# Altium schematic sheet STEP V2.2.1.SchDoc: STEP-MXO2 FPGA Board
size A3; Revision: V2.2; SheetNumber: 2; SheetTotal: 2; PageSetup: Record=PageOptions¦CenterHorizontal=True¦CenterVertical=True¦PrintScale=0.69¦XCorrection=1.00¦YCorrection=1.00¦PrintKind=0¦BorderSize=5000000¦LeftOffset=0¦BottomOffset=0¦Orientation=2¦PaperLength=1000¦PaperWidth=1000¦Scale=100¦PaperSource=7¦PrintQuality=-3¦MediaType=1¦DitherType=10¦PrintScaleMode=1¦PaperKind=A4¦PaperIndex=9; Function: FPGA,LEDs,Buttons,Switchs,RGB LEDs,Segments
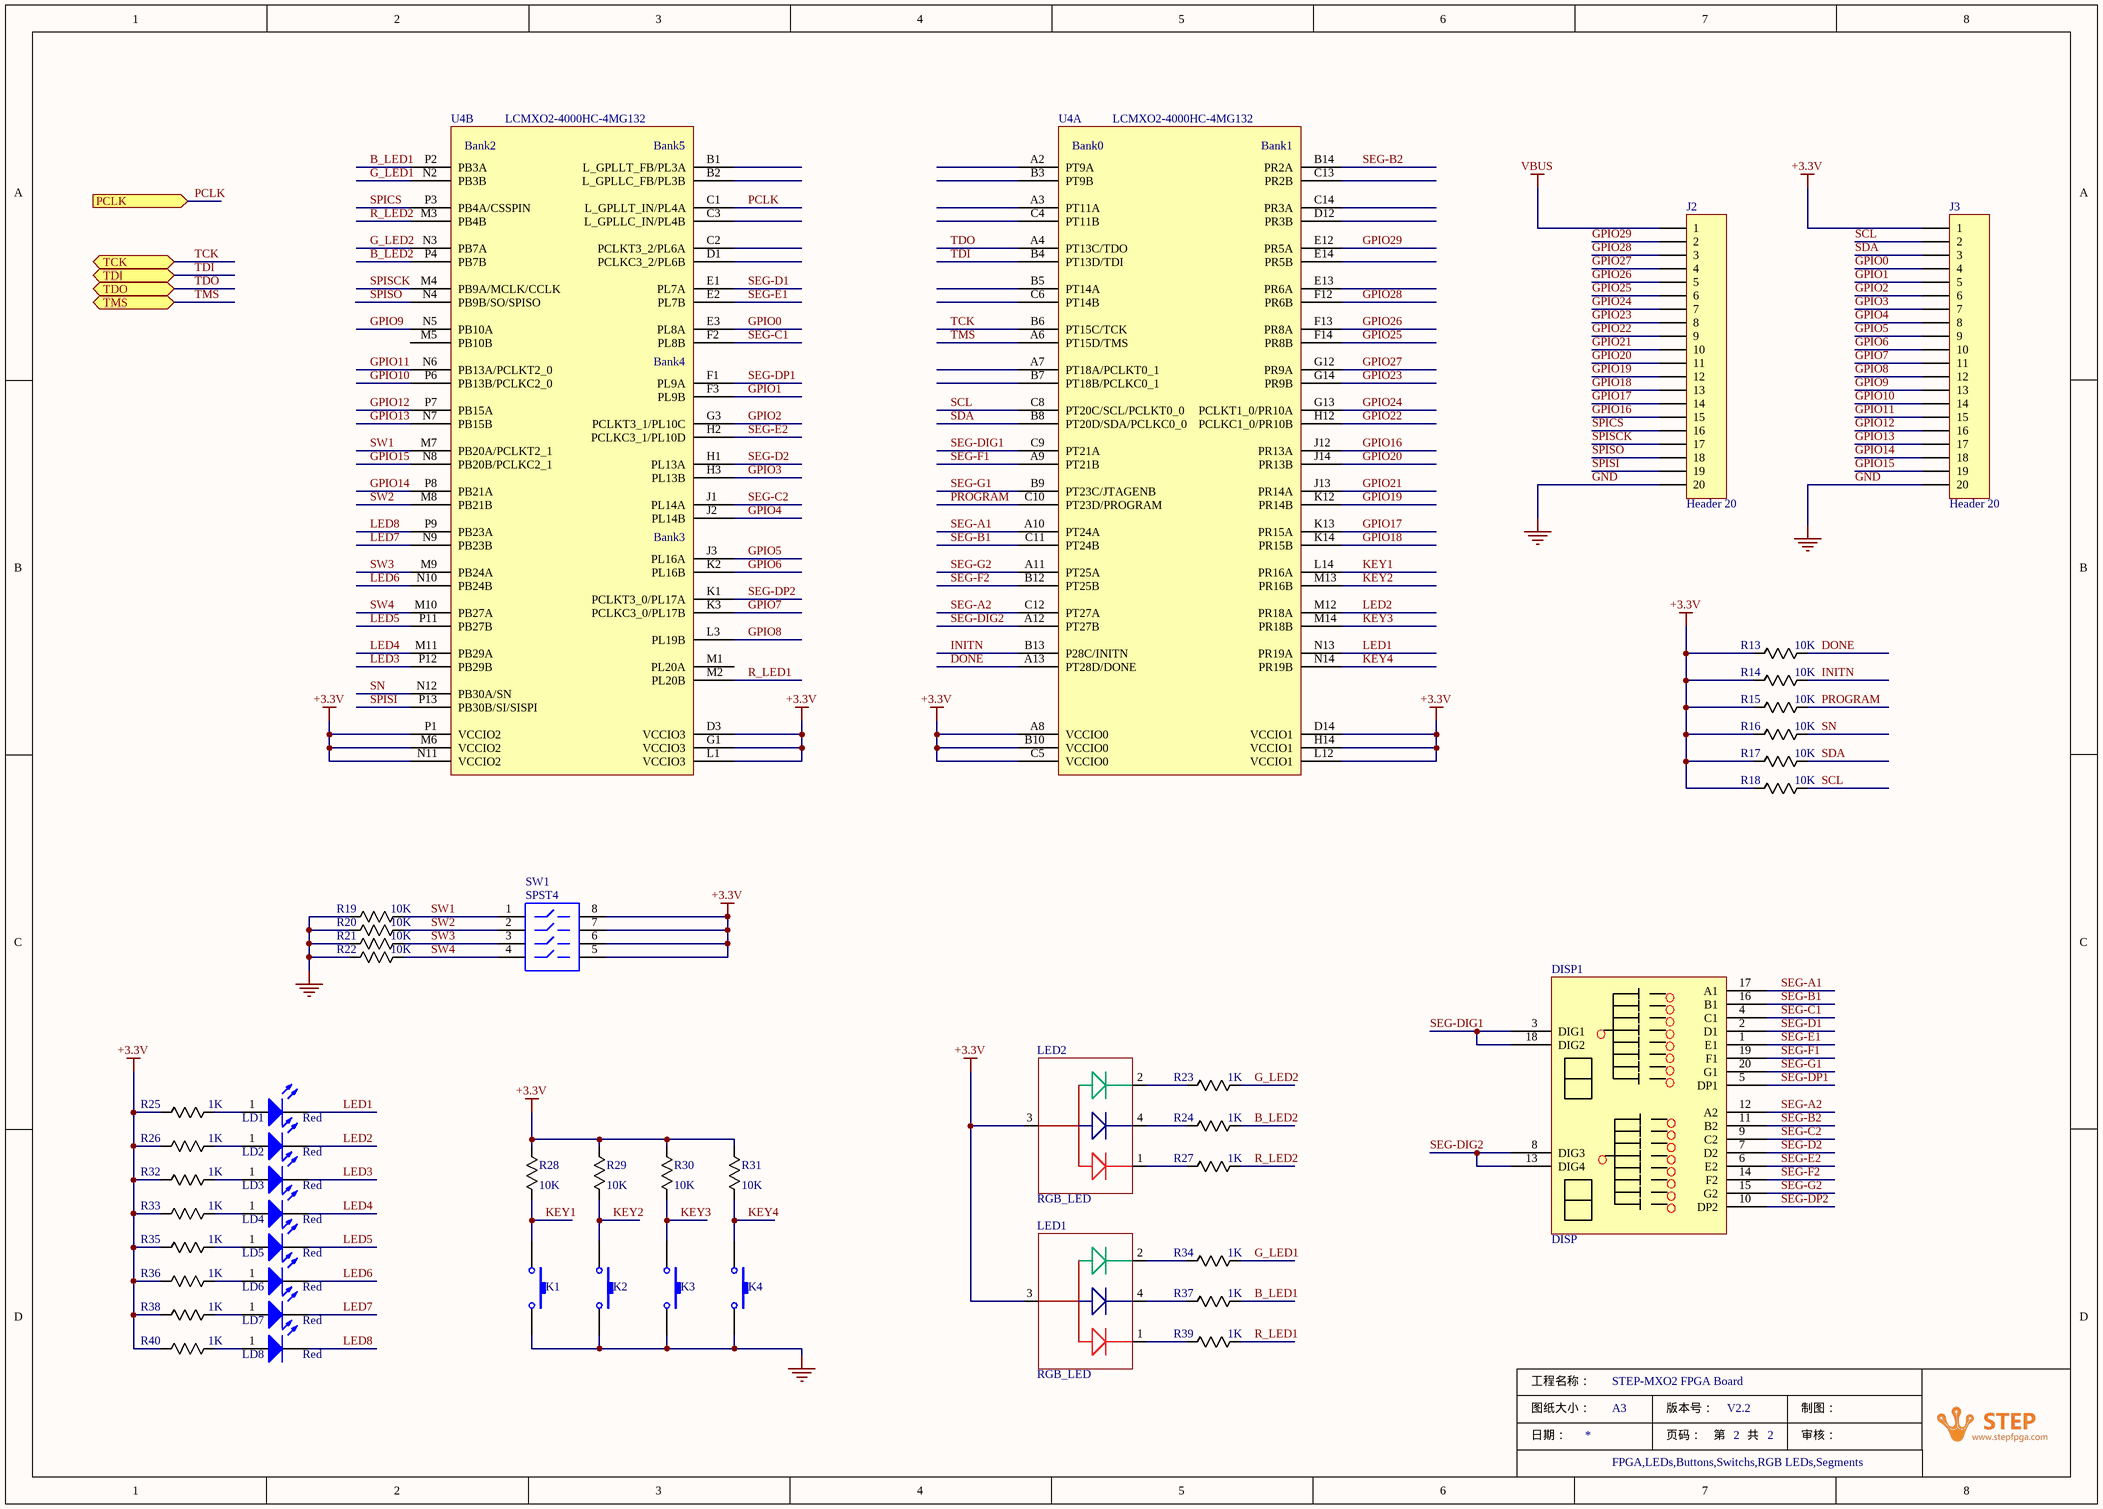
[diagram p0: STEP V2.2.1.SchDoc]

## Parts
DISP1  DISP  [SMD_LED_2*8bit_10*14]
J2  Header 20  [HDR1X20]
J3  Header 20  [HDR1X20]
K1  SW-PB  [SMD_KEY_3x4x2]  (value not drawn)
K2  SW-PB  [SMD_KEY_3x4x2]  (value not drawn)
K3  SW-PB  [SMD_KEY_3x4x2]  (value not drawn)
K4  SW-PB  [SMD_KEY_3x4x2]  (value not drawn)
LD1  Red  [LED0603]
LD2  Red  [LED0603]
LD3  Red  [LED0603]
LD4  Red  [LED0603]
LD5  Red  [LED0603]
LD6  Red  [LED0603]
LD7  Red  [LED0603]
LD8  Red  [LED0603]
LED1  RGB_LED  [SMD_RGB_LED_1.5*1.6]
LED2  RGB_LED  [SMD_RGB_LED_1.5*1.6]
R13  10K  [R0201]
R14  10K  [R0201]
R15  10K  [R0201]
R16  10K  [R0201]
R17  10K  [R0201]
R18  10K  [R0201]
R19  10K  [R0201]
R20  10K  [R0201]
R21  10K  [R0201]
R22  10K  [R0201]
R23  1K  [R0201]
R24  1K  [R0201]
R25  1K  [R0201]
R26  1K  [R0201]
R27  1K  [R0201]
R28  10K  [R0201]
R29  10K  [R0201]
R30  10K  [R0201]
R31  10K  [R0201]
R32  1K  [R0201]
R33  1K  [R0201]
R34  1K  [R0201]
R35  1K  [R0201]
R36  1K  [R0201]
R37  1K  [R0201]
R38  1K  [R0201]
R39  1K  [R0201]
R40  1K  [R0201]
SW1  SPST4  [SMD_KEY_4]
U4  LCMXO2-4000HC-4MG132  [CSBGA132]  (parts A,B of 3)

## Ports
PCLK (in), TCK (bidir), TDI (bidir), TDO (bidir), TMS (bidir)

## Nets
+3.3V: J3.1 LED1.3(COMMON_ANODE) LED2.3(COMMON_ANODE) R13.1 R14.1 R15.1 R16.1 R17.1 R18.1 R25.2 R26.2 R28.2 R29.2 R30.2 R31.2 R32.2 R33.2 R35.2 R36.2 R38.2 R40.2 SW1.5 SW1.6 SW1.7 SW1.8 U4.A8(VCCIO0) U4.B10(VCCIO0) U4.C5(VCCIO0) U4.D3(VCCIO3) U4.D14(VCCIO1) U4.G1(VCCIO3) U4.H14(VCCIO1) U4.L1(VCCIO3) U4.L12(VCCIO1) U4.M6(VCCIO2) U4.N11(VCCIO2) U4.P1(VCCIO2)
GND: J2.20 J3.20 K1.2 K2.2 K3.2 K4.2 R19.1 R20.1 R21.1 R22.1
VBUS: J2.1
B_LED1: R37.2 U4.P2(PB3A)
B_LED2: R24.2 U4.P4(PB7B)
DONE: R13.2 U4.A13(PT28D/DONE)
G_LED1: R34.2 U4.N2(PB3B)
G_LED2: R23.2 U4.N3(PB7A)
GPIO0: J3.4 U4.E3(PL8A)
GPIO1: J3.5 U4.F3(PL9B)
GPIO2: J3.6 U4.G3(PCLKT3_1/PL10C)
GPIO3: J3.7 U4.H3(PL13B)
GPIO4: J3.8 U4.J2(PL14B)
GPIO5: J3.9 U4.J3(PL16A)
GPIO6: J3.10 U4.K2(PL16B)
GPIO7: J3.11 U4.K3(PCLKC3_0/PL17B)
GPIO8: J3.12 U4.L3(PL19B)
GPIO9: J3.13 U4.N5(PB10A)
GPIO10: J3.14 U4.P6(PB13B/PCLKC2_0)
GPIO11: J3.15 U4.N6(PB13A/PCLKT2_0)
GPIO12: J3.16 U4.P7(PB15A)
GPIO13: J3.17 U4.N7(PB15B)
GPIO14: J3.18 U4.P8(PB21A)
GPIO15: J3.19 U4.N8(PB20B/PCLKC2_1)
GPIO16: J2.15 U4.J12(PR13A)
GPIO17: J2.14 U4.K13(PR15A)
GPIO18: J2.13 U4.K14(PR15B)
GPIO19: J2.12 U4.K12(PR14B)
GPIO20: J2.11 U4.J14(PR13B)
GPIO21: J2.10 U4.J13(PR14A)
GPIO22: J2.9 U4.H12(PCLKC1_0/PR10B)
GPIO23: J2.8 U4.G14(PR9B)
GPIO24: J2.7 U4.G13(PCLKT1_0/PR10A)
GPIO25: J2.6 U4.F14(PR8B)
GPIO26: J2.5 U4.F13(PR8A)
GPIO27: J2.4 U4.G12(PR9A)
GPIO28: J2.3 U4.F12(PR6B)
GPIO29: J2.2 U4.E12(PR5A)
INITN: R14.2 U4.B13(P28C/INITN)
KEY1: K1.1 R28.1 U4.L14(PR16A)
KEY2: K2.1 R29.1 U4.M13(PR16B)
KEY3: K3.1 R30.1 U4.M14(PR18B)
KEY4: K4.1 R31.1 U4.N14(PR19B)
LED1: LD1.2(K) U4.N13(PR19A)
LED2: LD2.2(K) U4.M12(PR18A)
LED3: LD3.2(K) U4.P12(PB29B)
LED4: LD4.2(K) U4.M11(PB29A)
LED5: LD5.2(K) U4.P11(PB27B)
LED6: LD6.2(K) U4.N10(PB24B)
LED7: LD7.2(K) U4.N9(PB23B)
LED8: LD8.2(K) U4.P9(PB23A)
PCLK: U4.C1(L_GPLLT_IN/PL4A) ; port PCLK
PROGRAM: R15.2 U4.C10(PT23D/PROGRAM)
R_LED1: R39.2 U4.M2(PL20B)
R_LED2: R27.2 U4.M3(PB4B)
SCL: J3.2 R18.2 U4.C8(PT20C/SCL/PCLKT0_0)
SDA: J3.3 R17.2 U4.B8(PT20D/SDA/PCLKC0_0)
SEG-A1: DISP1.17(A1) U4.A10(PT24A)
SEG-A2: DISP1.12(A2) U4.C12(PT27A)
SEG-B1: DISP1.16(B1) U4.C11(PT24B)
SEG-B2: DISP1.11(B2) U4.B14(PR2A)
SEG-C1: DISP1.4(C1) U4.F2(PL8B)
SEG-C2: DISP1.9(C2) U4.J1(PL14A)
SEG-D1: DISP1.2(D1) U4.E1(PL7A)
SEG-D2: DISP1.7(D2) U4.H1(PL13A)
SEG-DIG1: DISP1.3(DIG1) DISP1.18(DIG2) U4.C9(PT21A)
SEG-DIG2: DISP1.8(DIG3) DISP1.13(DIG4) U4.A12(PT27B)
SEG-DP1: DISP1.5(DP1) U4.F1(PL9A)
SEG-DP2: DISP1.10(DP2) U4.K1(PCLKT3_0/PL17A)
SEG-E1: DISP1.1(E1) U4.E2(PL7B)
SEG-E2: DISP1.6(E2) U4.H2(PCLKC3_1/PL10D)
SEG-F1: DISP1.19(F1) U4.A9(PT21B)
SEG-F2: DISP1.14(F2) U4.B12(PT25B)
SEG-G1: DISP1.20(G1) U4.B9(PT23C/JTAGENB)
SEG-G2: DISP1.15(G2) U4.A11(PT25A)
SN: R16.2 U4.N12(PB30A/SN)
SPICS: J2.16 U4.P3(PB4A/CSSPIN)
SPISCK: J2.17 U4.M4(PB9A/MCLK/CCLK)
SPISI: J2.19 U4.P13(PB30B/SI/SISPI)
SPISO: J2.18 U4.N4(PB9B/SO/SPISO)
SW1: R19.2 SW1.1 U4.M7(PB20A/PCLKT2_1)
SW2: R20.2 SW1.2 U4.M8(PB21B)
SW3: R21.2 SW1.3 U4.M9(PB24A)
SW4: R22.2 SW1.4 U4.M10(PB27A)
TCK: U4.B6(PT15C/TCK) ; port TCK
TDI: U4.B4(PT13D/TDI) ; port TDI
TDO: U4.A4(PT13C/TDO) ; port TDO
TMS: U4.A6(PT15D/TMS) ; port TMS
NetLD1_1: LD1.1(A) R25.1
NetLD2_1: LD2.1(A) R26.1
NetLD3_1: LD3.1(A) R32.1
NetLD4_1: LD4.1(A) R33.1
NetLD5_1: LD5.1(A) R35.1
NetLD6_1: LD6.1(A) R36.1
NetLD7_1: LD7.1(A) R38.1
NetLD8_1: LD8.1(A) R40.1
NetLED1_1: LED1.1(RED) R39.1
NetLED1_2: LED1.2(BLUE) R34.1
NetLED1_4: LED1.4(GREEN) R37.1
NetLED2_1: LED2.1(RED) R27.1
NetLED2_2: LED2.2(BLUE) R23.1
NetLED2_4: LED2.4(GREEN) R24.1

Not connected (* = marked no-connect by the designer): U4 A2(PT9A) A3(PT11A) A7(PT18A/PCLKT0_1) B1(L_GPLLT_FB/PL3A) B2(L_GPLLC_FB/PL3B) B3(PT9B) B5(PT14A) B7(PT18B/PCLKC0_1) C2(PCLKT3_2/PL6A) C3(L_GPLLC_IN/PL4B) C4(PT11B) C6(PT14B) C13(PR2B) C14(PR3A) D1(PCLKC3_2/PL6B) D12(PR3B) E13(PR6A) E14(PR5B) M1(PL20A) M5(PB10B)

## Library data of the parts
DISP1 = DISP: Seven Segment Display,Double; PartNumber: HLS-2021AX
J2 J3 = Header 20: Header, 20-Pin
K1-K4 = SW-PB: Switch
LD1-LD8 = LED: Typical INFRARED GaAs LED,1.8V,10mA,Red
LED1 LED2 = SMD_RGB_LED_1.5*1.6
R13-R40 = Res: 厚膜电阻器 - SMD xx OHM 5%; PartNumber: RC0603 JR-07 xx; Manufacture: Yageo
SW1 = SPST4: 贴片拨码开关 1.27MM间距 4位贴片平拨开关 4PIN; Manufacture: Wurth Electronics
U4 = LCMXO2-4000HC-4MG132: IC,LCMXO2-4000HC-4MG132 FPGA,csBGA132,4320 LUTs; Manufature: Lattice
